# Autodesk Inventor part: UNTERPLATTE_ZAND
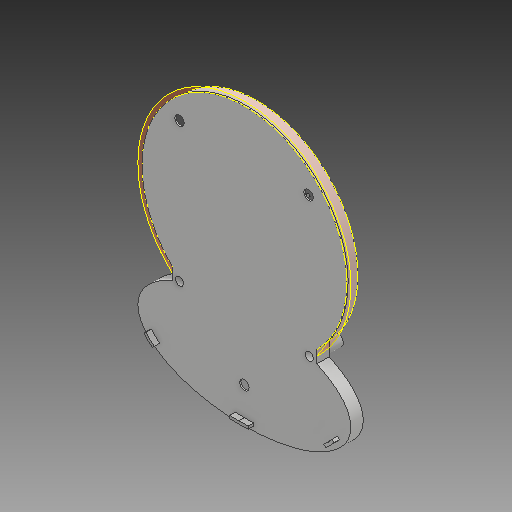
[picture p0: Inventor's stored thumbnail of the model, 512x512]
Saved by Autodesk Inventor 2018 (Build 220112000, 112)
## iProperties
Created: 2019-01
Part Number: UNTERPLATTE_ZAND
Material: Polypropylene (PP)
Document SubType Name: Modeling
Designer: zand
Density: 0.902188 g/cm^3
Appearance: Vorgabe
Mass: 32.0073 g
Surface Area: 700.365 cm^2
Volume: 35.4775 cm^3
Author: zand
Revision Number: 21LAST_VERSION
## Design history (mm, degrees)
feature "Basis1"
feature "Zusammengesetzt1"
node "Volumenkörper1"
node "Flä1"
